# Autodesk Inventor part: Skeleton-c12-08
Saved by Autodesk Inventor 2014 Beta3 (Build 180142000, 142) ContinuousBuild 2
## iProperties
Created: 2011-01
Part Number: Skeleton-c12-08
Material: Generic
Document SubType Name: Modeling
Designer: Thom Tremblay
Density: 1 g/cm^3
Appearance: Generic
_SkeletonDoc: Frame Skeleton File
_Version: 15.0.0
Author: Thom Tremblay
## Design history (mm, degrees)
sketch "Reference Skeleton"
  geometry: L1 through (325.691, 1070.446) direction (1, 0); L2 through (404.523, 1164.395) direction (1, 0); 34 other entities
  constraints: 10 horizontal
